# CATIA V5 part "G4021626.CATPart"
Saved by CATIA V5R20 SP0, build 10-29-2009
Part number: G4021626
Revision: 3
Definition: design
Nomenclature: G4021626
Source: made
Description: NOT SPECIFIED
Bounding box of the stored display mesh (mm): x -12 to 26, y -12.803 to 12.803, z -13 to 13
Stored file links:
  C:\Users\Raffaele\Desktop\3D X SITO CF\BOLEX\26-BUSH REF 402\G4021626.CATPart
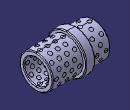
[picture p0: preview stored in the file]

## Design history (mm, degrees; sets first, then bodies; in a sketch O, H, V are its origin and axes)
Body1 "MANIFOLD_SOLID_BREP #11237" (main body)
  Solid1: solid without history
Body2 "MANIFOLD_SOLID_BREP #11380"
  Solid2: solid without history
Body3 "MANIFOLD_SOLID_BREP #11523"
  Solid3: solid without history
Body4 "MANIFOLD_SOLID_BREP #11666"
  Solid4: solid without history
Body5 "MANIFOLD_SOLID_BREP #11809"
  Solid5: solid without history
Body6 "MANIFOLD_SOLID_BREP #11954"
  Solid6: solid without history
Body7 "MANIFOLD_SOLID_BREP #12099"
  Solid7: solid without history
Body8 "MANIFOLD_SOLID_BREP #12244"
  Solid8: solid without history
Body9 "MANIFOLD_SOLID_BREP #12389"
  Solid9: solid without history
Body10 "MANIFOLD_SOLID_BREP #12534"
  Solid10: solid without history
Body11 "MANIFOLD_SOLID_BREP #12679"
  Solid11: solid without history
Body12 "MANIFOLD_SOLID_BREP #12824"
  Solid12: solid without history
Body13 "MANIFOLD_SOLID_BREP #12969"
  Solid13: solid without history
Body14 "MANIFOLD_SOLID_BREP #13114"
  Solid14: solid without history
Body15 "MANIFOLD_SOLID_BREP #13259"
  Solid15: solid without history
Body16 "MANIFOLD_SOLID_BREP #13404"
  Solid16: solid without history
Body17 "MANIFOLD_SOLID_BREP #13549"
  Solid17: solid without history
Body18 "MANIFOLD_SOLID_BREP #13692"
  Solid18: solid without history
Body19 "MANIFOLD_SOLID_BREP #13835"
  Solid19: solid without history
Body20 "MANIFOLD_SOLID_BREP #13978"
  Solid20: solid without history
Body21 "MANIFOLD_SOLID_BREP #14122"
  Solid21: solid without history
Body22 "MANIFOLD_SOLID_BREP #14267"
  Solid22: solid without history
Body23 "MANIFOLD_SOLID_BREP #14410"
  Solid23: solid without history
Body24 "MANIFOLD_SOLID_BREP #14554"
  Solid24: solid without history
Body25 "MANIFOLD_SOLID_BREP #14699"
  Solid25: solid without history
Body26 "MANIFOLD_SOLID_BREP #14844"
  Solid26: solid without history
Body27 "MANIFOLD_SOLID_BREP #14989"
  Solid27: solid without history
Body28 "MANIFOLD_SOLID_BREP #15134"
  Solid28: solid without history
Body29 "MANIFOLD_SOLID_BREP #15279"
  Solid29: solid without history
Body30 "MANIFOLD_SOLID_BREP #15424"
  Solid30: solid without history
Body31 "MANIFOLD_SOLID_BREP #15569"
  Solid31: solid without history
Body32 "MANIFOLD_SOLID_BREP #15712"
  Solid32: solid without history
Body33 "MANIFOLD_SOLID_BREP #15855"
  Solid33: solid without history
Body34 "MANIFOLD_SOLID_BREP #15998"
  Solid34: solid without history
Body35 "MANIFOLD_SOLID_BREP #16141"
  Solid35: solid without history
Body36 "MANIFOLD_SOLID_BREP #16284"
  Solid36: solid without history
Body37 "MANIFOLD_SOLID_BREP #16428"
  Solid37: solid without history
Body38 "MANIFOLD_SOLID_BREP #16573"
  Solid38: solid without history
Body39 "MANIFOLD_SOLID_BREP #16716"
  Solid39: solid without history
Body40 "MANIFOLD_SOLID_BREP #16860"
  Solid40: solid without history
Body41 "MANIFOLD_SOLID_BREP #17005"
  Solid41: solid without history
Body42 "MANIFOLD_SOLID_BREP #17150"
  Solid42: solid without history
Body43 "MANIFOLD_SOLID_BREP #17295"
  Solid43: solid without history
Body44 "MANIFOLD_SOLID_BREP #17440"
  Solid44: solid without history
Body45 "MANIFOLD_SOLID_BREP #17585"
  Solid45: solid without history
Body46 "MANIFOLD_SOLID_BREP #17730"
  Solid46: solid without history
Body47 "MANIFOLD_SOLID_BREP #17875"
  Solid47: solid without history
Body48 "MANIFOLD_SOLID_BREP #18020"
  Solid48: solid without history
Body49 "MANIFOLD_SOLID_BREP #18165"
  Solid49: solid without history
Body50 "MANIFOLD_SOLID_BREP #18310"
  Solid50: solid without history
Body51 "MANIFOLD_SOLID_BREP #18455"
  Solid51: solid without history
Body52 "MANIFOLD_SOLID_BREP #18600"
  Solid52: solid without history
Body53 "MANIFOLD_SOLID_BREP #18745"
  Solid53: solid without history
Body54 "MANIFOLD_SOLID_BREP #18888"
  Solid54: solid without history
Body55 "MANIFOLD_SOLID_BREP #19031"
  Solid55: solid without history
Body56 "MANIFOLD_SOLID_BREP #19174"
  Solid56: solid without history
Body57 "MANIFOLD_SOLID_BREP #19317"
  Solid57: solid without history
Body58 "MANIFOLD_SOLID_BREP #19460"
  Solid58: solid without history
Body59 "MANIFOLD_SOLID_BREP #19603"
  Solid59: solid without history
Body60 "MANIFOLD_SOLID_BREP #19746"
  Solid60: solid without history
Body61 "MANIFOLD_SOLID_BREP #19890"
  Solid61: solid without history
Body62 "MANIFOLD_SOLID_BREP #20035"
  Solid62: solid without history
Body63 "MANIFOLD_SOLID_BREP #20178"
  Solid63: solid without history
Body64 "MANIFOLD_SOLID_BREP #20322"
  Solid64: solid without history
Body65 "MANIFOLD_SOLID_BREP #20467"
  Solid65: solid without history
Body66 "MANIFOLD_SOLID_BREP #20612"
  Solid66: solid without history
Body67 "MANIFOLD_SOLID_BREP #20757"
  Solid67: solid without history
Body68 "MANIFOLD_SOLID_BREP #20902"
  Solid68: solid without history
Body69 "MANIFOLD_SOLID_BREP #21047"
  Solid69: solid without history
Body70 "MANIFOLD_SOLID_BREP #21192"
  Solid70: solid without history
Body71 "MANIFOLD_SOLID_BREP #21337"
  Solid71: solid without history
Body72 "MANIFOLD_SOLID_BREP #21480"
  Solid72: solid without history
Body73 "MANIFOLD_SOLID_BREP #21623"
  Solid73: solid without history
Body74 "MANIFOLD_SOLID_BREP #21766"
  Solid74: solid without history
Body75 "MANIFOLD_SOLID_BREP #21909"
  Solid75: solid without history
Body76 "MANIFOLD_SOLID_BREP #22052"
  Solid76: solid without history
Body77 "MANIFOLD_SOLID_BREP #22196"
  Solid77: solid without history
Body78 "MANIFOLD_SOLID_BREP #22341"
  Solid78: solid without history
Body79 "MANIFOLD_SOLID_BREP #22484"
  Solid79: solid without history
Body80 "MANIFOLD_SOLID_BREP #22628"
  Solid80: solid without history
Body81 "MANIFOLD_SOLID_BREP #22773"
  Solid81: solid without history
